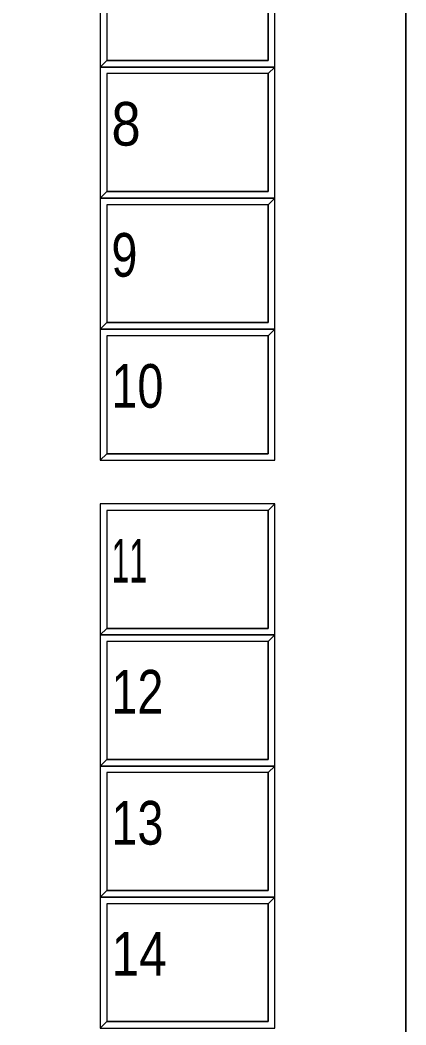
# Model space of a CAD drawing. Extents: x 95906.8 to 95923.6, y 90964.8 to 90972.8.
# Drawn here: x 95917.949 to 95918.832, y 90967.969 to 90970.269 of the extents above; entities that cross this region are included whole.
import ezdxf

# ---------------------------------------------------------------- set-up
doc = ezdxf.new("R2010")
doc.units = 0
doc.header["$LTSCALE"] = 0.019
for name, color, linetype, lineweight in [('1', 7, 'Continuous', 25), ('11', 7, 'Continuous', 25), ('2', 7, 'Continuous', 13), ('3', 7, 'Continuous', 25), ('6', 7, 'Continuous', 35), ('7', 7, 'Continuous', 35)]:
    doc.layers.add(name, color=color, linetype=linetype, lineweight=lineweight)

msp = doc.modelspace()

# ---------------------------------------------------------------- linework, layer by layer
at = {"layer": '1'}
for points in [[(95918.1323, 90970.1617), (95918.5323, 90970.1617), (95918.5323, 90970.4617), (95918.1323, 90970.4617)], [(95918.1323, 90969.8617), (95918.5323, 90969.8617), (95918.5323, 90970.1617), (95918.1323, 90970.1617)], [(95918.1323, 90969.5617), (95918.5323, 90969.5617), (95918.5323, 90969.8617), (95918.1323, 90969.8617)], [(95918.1323, 90969.2617), (95918.5323, 90969.2617), (95918.5323, 90969.5617), (95918.1323, 90969.5617)], [(95918.1323, 90968.8617), (95918.5323, 90968.8617), (95918.5323, 90969.1617), (95918.1323, 90969.1617)], [(95918.1323, 90968.5617), (95918.5323, 90968.5617), (95918.5323, 90968.8617), (95918.1323, 90968.8617)], [(95918.1323, 90968.2617), (95918.5323, 90968.2617), (95918.5323, 90968.5617), (95918.1323, 90968.5617)], [(95918.1323, 90967.9617), (95918.5323, 90967.9617), (95918.5323, 90968.2617), (95918.1323, 90968.2617)]]:
    msp.add_lwpolyline(points, close=True, dxfattribs=at)
at = {"layer": '11'}
for points in [[(95918.1473, 90970.1767), (95918.5173, 90970.1767), (95918.5173, 90970.4467), (95918.1473, 90970.4467)], [(95918.1473, 90969.8767), (95918.5173, 90969.8767), (95918.5173, 90970.1467), (95918.1473, 90970.1467)], [(95918.1473, 90969.5767), (95918.5173, 90969.5767), (95918.5173, 90969.8467), (95918.1473, 90969.8467)], [(95918.1473, 90969.2767), (95918.5173, 90969.2767), (95918.5173, 90969.5467), (95918.1473, 90969.5467)], [(95918.1473, 90968.8767), (95918.5173, 90968.8767), (95918.5173, 90969.1467), (95918.1473, 90969.1467)], [(95918.1473, 90968.5767), (95918.5173, 90968.5767), (95918.5173, 90968.8467), (95918.1473, 90968.8467)], [(95918.1473, 90968.2767), (95918.5173, 90968.2767), (95918.5173, 90968.5467), (95918.1473, 90968.5467)], [(95918.1473, 90967.9767), (95918.5173, 90967.9767), (95918.5173, 90968.2467), (95918.1473, 90968.2467)]]:
    msp.add_lwpolyline(points, close=True, dxfattribs=at)
at = {"layer": '2'}
for points in [[(95918.1323, 90970.4617), (95918.1323, 90970.1617), (95918.1473, 90970.1767), (95918.1473, 90970.4467), (95918.5173, 90970.4467), (95918.5323, 90970.4617)], [(95918.1323, 90970.1617), (95918.1323, 90969.8617), (95918.1473, 90969.8767), (95918.1473, 90970.1467), (95918.5173, 90970.1467), (95918.5323, 90970.1617)], [(95918.1323, 90969.8617), (95918.1323, 90969.5617), (95918.1473, 90969.5767), (95918.1473, 90969.8467), (95918.5173, 90969.8467), (95918.5323, 90969.8617)], [(95918.1323, 90969.5617), (95918.1323, 90969.2617), (95918.1473, 90969.2767), (95918.1473, 90969.5467), (95918.5173, 90969.5467), (95918.5323, 90969.5617)], [(95918.1323, 90969.1617), (95918.1323, 90968.8617), (95918.1473, 90968.8767), (95918.1473, 90969.1467), (95918.5173, 90969.1467), (95918.5323, 90969.1617)], [(95918.1323, 90968.8617), (95918.1323, 90968.5617), (95918.1473, 90968.5767), (95918.1473, 90968.8467), (95918.5173, 90968.8467), (95918.5323, 90968.8617)], [(95918.1323, 90968.5617), (95918.1323, 90968.2617), (95918.1473, 90968.2767), (95918.1473, 90968.5467), (95918.5173, 90968.5467), (95918.5323, 90968.5617)], [(95918.1323, 90968.2617), (95918.1323, 90967.9617), (95918.1473, 90967.9767), (95918.1473, 90968.2467), (95918.5173, 90968.2467), (95918.5323, 90968.2617)]]:
    msp.add_lwpolyline(points, close=True, dxfattribs=at)
at = {"layer": '3'}
for points in [[(95918.1323, 90970.1617), (95918.5323, 90970.1617), (95918.5323, 90970.4617), (95918.5173, 90970.4467), (95918.5173, 90970.1767), (95918.1473, 90970.1767)], [(95918.1323, 90969.8617), (95918.5323, 90969.8617), (95918.5323, 90970.1617), (95918.5173, 90970.1467), (95918.5173, 90969.8767), (95918.1473, 90969.8767)], [(95918.1323, 90969.5617), (95918.5323, 90969.5617), (95918.5323, 90969.8617), (95918.5173, 90969.8467), (95918.5173, 90969.5767), (95918.1473, 90969.5767)], [(95918.1323, 90969.2617), (95918.5323, 90969.2617), (95918.5323, 90969.5617), (95918.5173, 90969.5467), (95918.5173, 90969.2767), (95918.1473, 90969.2767)], [(95918.1323, 90968.8617), (95918.5323, 90968.8617), (95918.5323, 90969.1617), (95918.5173, 90969.1467), (95918.5173, 90968.8767), (95918.1473, 90968.8767)], [(95918.1323, 90968.5617), (95918.5323, 90968.5617), (95918.5323, 90968.8617), (95918.5173, 90968.8467), (95918.5173, 90968.5767), (95918.1473, 90968.5767)], [(95918.1323, 90968.2617), (95918.5323, 90968.2617), (95918.5323, 90968.5617), (95918.5173, 90968.5467), (95918.5173, 90968.2767), (95918.1473, 90968.2767)], [(95918.1323, 90967.9617), (95918.5323, 90967.9617), (95918.5323, 90968.2617), (95918.5173, 90968.2467), (95918.5173, 90967.9767), (95918.1473, 90967.9767)]]:
    msp.add_lwpolyline(points, close=True, dxfattribs=at)
at = {"layer": '7'}
msp.add_lwpolyline([(95906.8323, 90972.7617), (95918.8323, 90972.7617), (95918.8323, 90964.7617), (95906.8323, 90964.7617)], close=True, dxfattribs=at)

# ---------------------------------------------------------------- texts
at = {"layer": '6'}
for s, width, p in [('8', 0.9, (95918.1581, 90969.9818)), ('9', 0.8, (95918.1581, 90969.6818)), ('10', 0.8, (95918.1581, 90969.3818)), ('11', 0.55, (95918.1581, 90968.9818)), ('12', 0.8, (95918.1581, 90968.6818)), ('13', 0.8, (95918.1581, 90968.3818)), ('14', 0.85, (95918.1581, 90968.0818))]:
    msp.add_text(s, height=0.1, dxfattribs=dict(at, width=width)).set_placement(p)

doc.saveas('drawing.dxf')
